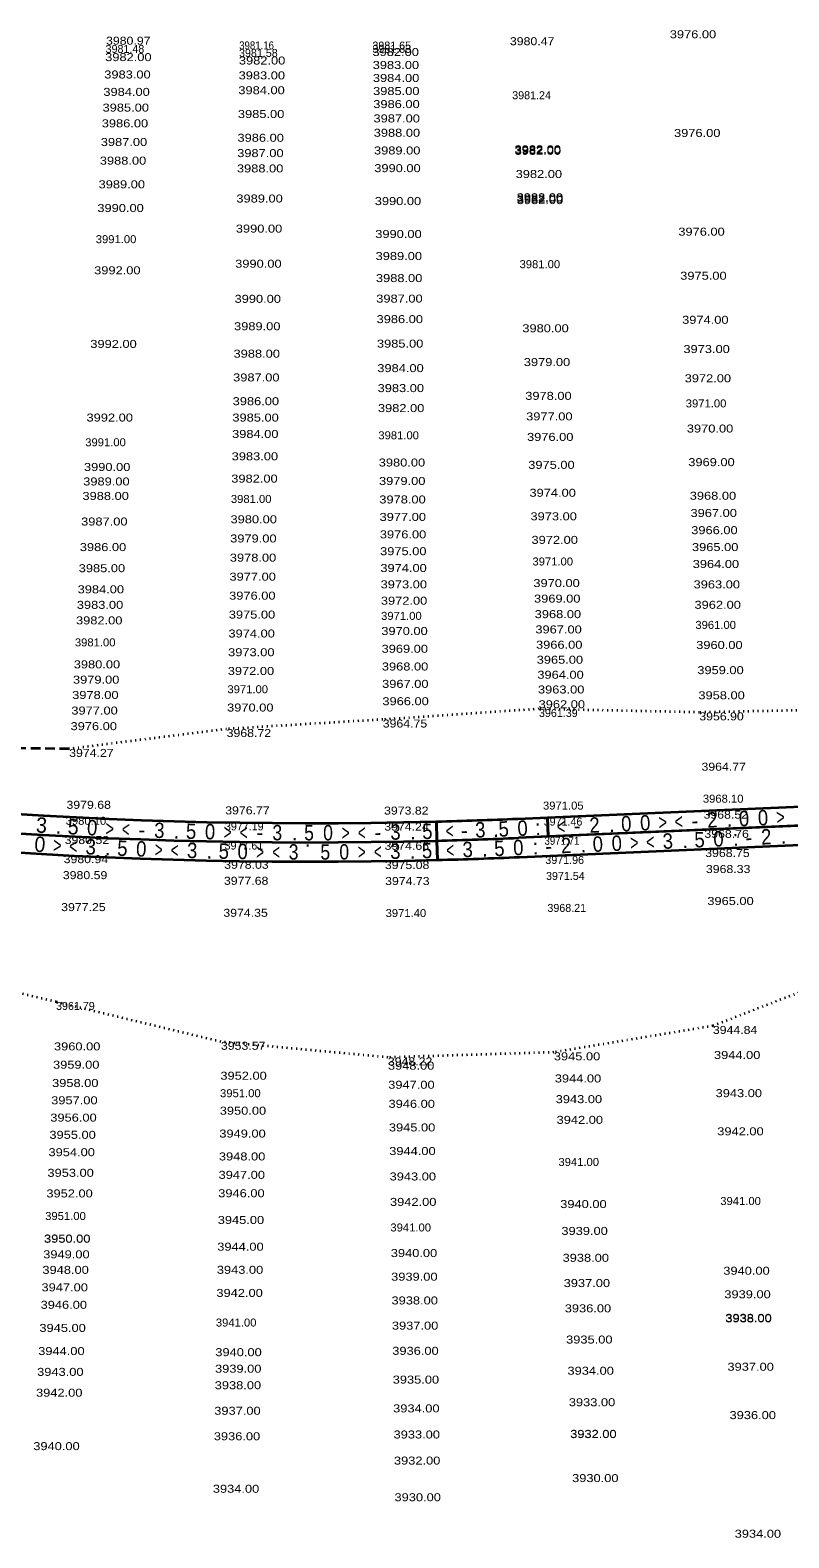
# Model space of a CAD drawing. Extents: x 49942 to 56479, y 47140 to 53283.
# Drawn here: x 52171 to 52645, y 49323 to 50265 of the extents above; entities that cross this region are included whole.
import ezdxf
from ezdxf.enums import TextEntityAlignment as Align

# ---------------------------------------------------------------- set-up
doc = ezdxf.new("R2010")
doc.units = 0
doc.header["$LTSCALE"] = 2
doc.linetypes.add('DOTTED', pattern=[1.5, 0.3, -1.2])
doc.linetypes.add('MEDIUM_DASHED', pattern=[4.5, 3, -1.5])
doc.layers.add('29', color=7, linetype='Continuous')
doc.layers.add('59', color=7, linetype='Continuous', lineweight=35)
doc.layers.add('63', color=7, linetype='Continuous', lineweight=35)

msp = doc.modelspace()

# ---------------------------------------------------------------- linework, layer by layer
at = {"layer": '59', "linetype": 'DOTTED'}
for p, q in [((52488.825, 49841.2), (52391.172, 49834.614)), ((52589.011, 49839.074), (52488.825, 49841.2)), ((52689.019, 49841.052), (52589.011, 49839.074)), ((52293.624, 49828.673), (52195.222, 49816.237)), ((52391.172, 49834.614), (52293.624, 49828.673)), ((52187.039, 49658.165), (52085.276, 49682.412)), ((52695.936, 49681.3), (52597.493, 49643.178)), ((52290.058, 49633.276), (52187.039, 49658.165)), ((52597.493, 49643.178), (52498.113, 49626.686)), ((52394.388, 49623.506), (52290.058, 49633.276)), ((52498.113, 49626.686), (52394.388, 49623.506))]:
    msp.add_line(p, q, dxfattribs=at)
at = {"layer": '59', "linetype": 'MEDIUM_DASHED'}
msp.add_line((52195.222, 49816.237), (52096.806, 49817.413), dxfattribs=at)
at = {"layer": '63'}
for p, q in [((52424.705, 49770.881), (52425.019, 49758.885)), ((52425.019, 49758.885), (52424.705, 49770.881)), ((52425.333, 49746.889), (52425.019, 49758.885)), ((52425.019, 49758.885), (52425.333, 49746.889))]:
    msp.add_line(p, q, dxfattribs=at)
msp.add_lwpolyline([(52494.091, 49773.45), (53576.866, 49820.33), (53577.385, 49808.342), (52494.61, 49761.461)], close=True, dxfattribs=at)
for points in [[(52475.536, 49772.646), (52494.091, 49773.45), (52494.61, 49761.461), (52476.055, 49760.658)], [(52476.574, 49748.669), (52680.665, 49757.505), (52680.146, 49769.494), (52476.055, 49760.658)]]:
    msp.add_lwpolyline(points, dxfattribs=at)
for radius, start, end in [(2975.18, 246.32672, 271.49967), (2987.18, 246.32672, 271.49967), (2987.18, 246.32672, 271.49967), (2999.18, 246.32672, 271.49967), (2975.18, 271.49967, 272.47917), (2987.18, 271.49967, 272.47917), (2987.18, 271.49967, 272.47917), (2999.18, 271.49967, 272.47917)]:
    msp.add_arc((52346.841, 52745.042), radius, start, end, dxfattribs=at)

# ---------------------------------------------------------------- texts
at = {"layer": '29'}
for s, width, p in [('3976.00', 1.2, (52570.56, 50260.218)), ('3980.97', 1.15, (52218.256, 50256.188)), ('3981.16', 0.9, (52301.463, 50253.276)), ('3982.00', 1.2, (52384.782, 50249.128)), ('3980.47', 1.15, (52470.654, 50255.892)), ('3982.00', 1.2, (52217.726, 50245.956)), ('3982.00', 1.2, (52301.29, 50243.822)), ('3983.00', 1.2, (52384.906, 50241.023)), ('3983.00', 1.2, (52217.164, 50235.09)), ('3983.00', 1.2, (52301.121, 50234.537)), ('3984.00', 1.2, (52385.029, 50232.918)), ('3984.00', 1.2, (52216.601, 50224.224)), ('3984.00', 1.2, (52300.952, 50225.251)), ('3985.00', 1.2, (52385.153, 50224.762)), ('3985.00', 1.2, (52216.093, 50214.404)), ('3985.00', 1.2, (52300.681, 50210.407)), ('3986.00', 1.2, (52385.277, 50216.606)), ('3986.00', 1.2, (52215.585, 50204.584)), ('3987.00', 1.2, (52385.414, 50207.645)), ('3987.00', 1.2, (52214.981, 50192.932)), ('3986.00', 1.2, (52300.41, 50195.563)), ('3988.00', 1.2, (52385.55, 50198.683)), ('3976.00', 1.2, (52573.23, 50198.563)), ('3988.00', 1.2, (52214.378, 50181.279)), ('3987.00', 1.2, (52300.235, 50185.987)), ('3989.00', 1.2, (52385.719, 50187.629)), ('3982.00', 1.2, (52473.577, 50188.372)), ('3982.00', 1.2, (52473.587, 50188.149)), ('3982.00', 1.2, (52473.597, 50187.925)), ('3982.00', 1.2, (52473.608, 50187.668)), ('3982.00', 1.2, (52473.619, 50187.412)), ('3988.00', 1.2, (52300.06, 50176.41)), ('3990.00', 1.2, (52385.887, 50176.575)), ('3982.00', 1.2, (52474.247, 50172.906)), ('3989.00', 1.2, (52213.612, 50166.475)), ('3989.00', 1.2, (52299.717, 50157.607)), ('3990.00', 1.2, (52386.2, 50156.01)), ('3982.00', 1.2, (52474.875, 50158.401)), ('3982.00', 1.2, (52474.914, 50157.508)), ('3982.00', 1.2, (52474.952, 50156.614)), ('3990.00', 1.2, (52212.845, 50151.671)), ('3990.00', 1.2, (52299.374, 50138.802)), ('3990.00', 1.2, (52386.514, 50135.444)), ('3976.00', 1.2, (52575.899, 50136.908)), ('3991.00', 1.05, (52211.838, 50132.213)), ('3990.00', 1.2, (52298.974, 50116.873)), ('3989.00', 1.2, (52386.723, 50121.672)), ('3981.00', 1.05, (52476.686, 50116.578)), ('3992.00', 1.2, (52210.831, 50112.755)), ('3988.00', 1.2, (52386.933, 50107.9)), ('3975.00', 1.2, (52577.092, 50109.368)), ('3990.00', 1.2, (52298.574, 50094.944)), ('3987.00', 1.2, (52387.128, 50095.08)), ('3989.00', 1.2, (52298.261, 50077.808)), ('3986.00', 1.2, (52387.324, 50082.26)), ('3974.00', 1.2, (52578.284, 50081.829)), ('3980.00', 1.2, (52478.419, 50076.542)), ('3992.00', 1.2, (52208.45, 50066.757)), ('3988.00', 1.2, (52297.948, 50060.673)), ('3985.00', 1.2, (52387.557, 50066.954)), ('3973.00', 1.2, (52579.075, 50063.564)), ('3984.00', 1.2, (52387.79, 50051.648)), ('3979.00', 1.2, (52479.333, 50055.428)), ('3987.00', 1.2, (52297.677, 50045.83)), ('3972.00', 1.2, (52579.866, 50045.299)), ('3986.00', 1.2, (52297.407, 50030.987)), ('3983.00', 1.2, (52387.98, 50039.165)), ('3978.00', 1.2, (52480.248, 50034.314)), ('3982.00', 1.2, (52388.17, 50026.681)), ('3977.00', 1.2, (52480.803, 50021.49)), ('3971.00', 1.05, (52580.545, 50029.603)), ('3992.00', 1.2, (52206.068, 50020.759)), ('3985.00', 1.2, (52297.22, 50020.75)), ('3970.00', 1.2, (52581.225, 50013.907)), ('3991.00', 1.05, (52205.269, 50005.321)), ('3984.00', 1.2, (52297.033, 50010.513)), ('3981.00', 1.05, (52388.429, 50009.678)), ('3976.00', 1.2, (52481.358, 50008.666)), ('3983.00', 1.2, (52296.779, 49996.566)), ('3969.00', 1.2, (52582.134, 49992.906)), ('3990.00', 1.2, (52204.47, 49989.883)), ('3980.00', 1.2, (52388.688, 49992.675)), ('3975.00', 1.2, (52482.113, 49991.219)), ('3989.00', 1.2, (52204.002, 49980.838)), ('3982.00', 1.2, (52296.524, 49982.619)), ('3979.00', 1.2, (52388.864, 49981.153)), ('3988.00', 1.2, (52203.533, 49971.793)), ('3981.00', 1.05, (52296.292, 49969.913)), ('3978.00', 1.2, (52389.04, 49969.591)), ('3974.00', 1.2, (52482.869, 49973.772)), ('3968.00', 1.2, (52583.043, 49971.906)), ('3987.00', 1.2, (52202.706, 49955.817)), ('3980.00', 1.2, (52296.06, 49957.206)), ('3977.00', 1.2, (52389.206, 49958.683)), ('3973.00', 1.2, (52483.506, 49959.058)), ('3967.00', 1.2, (52583.509, 49961.154)), ('3976.00', 1.2, (52389.372, 49947.775)), ('3966.00', 1.2, (52583.974, 49950.403)), ('3986.00', 1.2, (52201.879, 49939.84)), ('3979.00', 1.2, (52295.842, 49945.221)), ('3975.00', 1.2, (52389.532, 49937.269)), ('3972.00', 1.2, (52484.143, 49944.344)), ('3965.00', 1.2, (52584.432, 49939.842)), ('3978.00', 1.2, (52295.623, 49933.235)), ('3971.00', 1.05, (52484.727, 49930.849)), ('3964.00', 1.2, (52584.889, 49929.281)), ('3985.00', 1.2, (52201.196, 49926.648)), ('3977.00', 1.2, (52295.406, 49921.368)), ('3974.00', 1.2, (52389.692, 49926.762)), ('3984.00', 1.2, (52200.513, 49913.455)), ('3976.00', 1.2, (52295.19, 49909.501)), ('3973.00', 1.2, (52389.848, 49916.549)), ('3970.00', 1.2, (52485.312, 49917.354)), ('3963.00', 1.2, (52585.441, 49916.53)), ('3983.00', 1.2, (52200.011, 49903.749)), ('3972.00', 1.2, (52390.003, 49906.336)), ('3969.00', 1.2, (52485.732, 49907.653)), ('3962.00', 1.2, (52585.993, 49903.779)), ('3982.00', 1.2, (52199.508, 49894.043)), ('3975.00', 1.2, (52294.974, 49897.675)), ('3971.00', 1.05, (52390.148, 49896.87)), ('3968.00', 1.2, (52486.152, 49897.952)), ('3961.00', 1.05, (52586.537, 49891.227)), ('3981.00', 1.05, (52198.797, 49880.309)), ('3974.00', 1.2, (52294.758, 49885.849)), ('3970.00', 1.2, (52390.292, 49887.403)), ('3967.00', 1.2, (52486.566, 49888.393)), ('3973.00', 1.2, (52294.545, 49874.149)), ('3969.00', 1.2, (52390.461, 49876.317)), ('3966.00', 1.2, (52486.979, 49878.835)), ('3960.00', 1.2, (52587.08, 49878.675)), ('3980.00', 1.2, (52198.086, 49866.574)), ('3972.00', 1.2, (52294.331, 49862.448)), ('3968.00', 1.2, (52390.63, 49865.23)), ('3965.00', 1.2, (52487.385, 49869.458)), ('3959.00', 1.2, (52587.76, 49862.963)), ('3979.00', 1.2, (52197.591, 49857.009)), ('3967.00', 1.2, (52390.795, 49854.387)), ('3964.00', 1.2, (52487.791, 49860.08)), ('3978.00', 1.2, (52197.096, 49847.444)), ('3971.00', 1.05, (52294.123, 49851.023)), ('3966.00', 1.2, (52390.96, 49843.544)), ('3963.00', 1.2, (52488.19, 49850.865)), ('3958.00', 1.2, (52588.441, 49847.251)), ('3977.00', 1.2, (52196.592, 49837.704)), ('3970.00', 1.2, (52293.914, 49839.599)), ('3962.00', 1.2, (52488.589, 49841.65)), ('3956.90', 1.15, (52589.011, 49834.074)), ('3976.00', 1.2, (52196.088, 49827.965)), ('3968.72', 1.15, (52293.624, 49823.673)), ('3964.75', 1.15, (52391.172, 49829.614)), ('3974.27', 1.15, (52195.222, 49811.237)), ('3964.77', 1.15, (52590.372, 49802.646)), ('3979.68', 1.15, (52193.544, 49778.827)), ('3971.05', 1.05, (52491.33, 49778.339)), ('3968.10', 1.05, (52591.237, 49782.665)), ('3980.10', 1.05, (52193.027, 49768.84)), ('3976.77', 1.15, (52292.742, 49775.355)), ('3973.82', 1.15, (52392.001, 49775.206)), ('3968.52', 1.15, (52591.669, 49772.675)), ('3974.24', 1.15, (52392.153, 49765.207)), ('3968.76', 1.15, (52592.188, 49760.686)), ('3980.52', 1.15, (52192.407, 49756.856)), ('3974.66', 1.15, (52392.336, 49753.208)), ('3971.71', 0.9, (52492.282, 49756.36)), ('3968.75', 1.15, (52592.707, 49748.697)), ('3980.94', 1.15, (52191.786, 49744.872)), ('3978.03', 1.15, (52292.122, 49741.361)), ('3975.08', 1.15, (52392.519, 49741.209)), ('3968.33', 1.15, (52593.14, 49738.706)), ('3980.59', 1.15, (52191.269, 49734.886)), ('3977.68', 1.15, (52291.939, 49731.362)), ('3974.73', 1.15, (52392.671, 49731.211)), ('3977.25', 1.15, (52190.235, 49714.912)), ('3974.35', 1.15, (52291.574, 49711.366)), ('3971.40', 1.05, (52392.976, 49711.213)), ('3965.00', 1.2, (52594.005, 49718.725)), ('3944.84', 1.15, (52597.493, 49638.178)), ('3960.00', 1.2, (52185.73, 49627.887)), ('3953.57', 1.15, (52290.058, 49628.276)), ('3959.00', 1.2, (52185.138, 49616.459)), ('3948.22', 1.15, (52394.388, 49618.506)), ('3945.00', 1.2, (52498.113, 49621.686)), ('3944.00', 1.2, (52598.171, 49622.522)), ('3952.00', 1.2, (52289.717, 49609.574)), ('3948.00', 1.2, (52394.428, 49615.851)), ('3944.00', 1.2, (52498.711, 49607.873)), ('3958.00', 1.2, (52184.547, 49605.032)), ('3951.00', 1.05, (52289.518, 49598.647)), ('3947.00', 1.2, (52394.609, 49603.935)), ('3943.00', 1.2, (52599.203, 49598.682)), ('3957.00', 1.2, (52183.987, 49594.215)), ('3946.00', 1.2, (52394.791, 49592.02)), ('3943.00', 1.2, (52499.271, 49594.936)), ('3956.00', 1.2, (52183.427, 49583.398)), ('3950.00', 1.2, (52289.318, 49587.719)), ('3942.00', 1.2, (52499.831, 49581.999)), ('3955.00', 1.2, (52182.87, 49572.648)), ('3949.00', 1.2, (52289.057, 49573.431)), ('3945.00', 1.2, (52395.016, 49577.27)), ('3942.00', 1.2, (52600.235, 49574.841)), ('3954.00', 1.2, (52182.309, 49561.799)), ('3944.00', 1.2, (52395.24, 49562.521)), ('3948.00', 1.2, (52288.797, 49559.142)), ('3941.00', 1.05, (52500.97, 49555.695)), ('3953.00', 1.2, (52181.642, 49548.913)), ('3947.00', 1.2, (52288.587, 49547.645)), ('3943.00', 1.2, (52395.482, 49546.634)), ('3952.00', 1.2, (52180.975, 49536.027)), ('3946.00', 1.2, (52288.377, 49536.149)), ('3941.00', 1.05, (52602.121, 49531.289)), ('3951.00', 1.05, (52180.245, 49521.942)), ('3942.00', 1.2, (52395.724, 49530.747)), ('3940.00', 1.2, (52502.109, 49529.392)), ('3945.00', 1.2, (52288.072, 49519.455)), ('3941.00', 1.05, (52395.968, 49514.768)), ('3939.00', 1.2, (52502.836, 49512.605)), ('3950.00', 1.2, (52179.508, 49507.702)), ('3950.00', 1.2, (52179.512, 49507.783)), ('3950.00', 1.2, (52179.516, 49507.857)), ('3949.00', 1.2, (52179.005, 49497.987)), ('3944.00', 1.2, (52287.768, 49502.762)), ('3940.00', 1.2, (52396.211, 49498.789)), ('3938.00', 1.2, (52503.563, 49495.817)), ('3948.00', 1.2, (52178.502, 49488.272)), ('3943.00', 1.2, (52287.504, 49488.315)), ('3940.00', 1.2, (52604.006, 49487.738)), ('3947.00', 1.2, (52177.938, 49477.365)), ('3939.00', 1.2, (52396.436, 49484.013)), ('3937.00', 1.2, (52504.246, 49480.034)), ('3946.00', 1.2, (52177.373, 49466.457)), ('3942.00', 1.2, (52287.241, 49473.869)), ('3938.00', 1.2, (52396.662, 49469.175)), ('3939.00', 1.2, (52604.643, 49473.035)), ('3936.00', 1.2, (52504.93, 49464.25)), ('3938.00', 1.2, (52605.281, 49458.289)), ('3938.00', 1.2, (52605.289, 49458.12)), ('3938.00', 1.2, (52605.296, 49457.951)), ('3945.00', 1.2, (52176.625, 49452.006)), ('3941.00', 1.05, (52286.903, 49455.362)), ('3937.00', 1.2, (52396.902, 49453.439)), ('3944.00', 1.2, (52175.877, 49437.555)), ('3936.00', 1.2, (52397.142, 49437.704)), ('3935.00', 1.2, (52505.774, 49444.756)), ('3940.00', 1.2, (52286.565, 49436.854)), ('3937.00', 1.2, (52606.604, 49427.746)), ('3943.00', 1.2, (52175.204, 49424.55)), ('3939.00', 1.2, (52286.377, 49426.53)), ('3935.00', 1.2, (52397.415, 49419.717)), ('3934.00', 1.2, (52506.618, 49425.262)), ('3942.00', 1.2, (52174.53, 49411.544)), ('3938.00', 1.2, (52286.188, 49416.206)), ('3937.00', 1.2, (52285.897, 49400.261)), ('3934.00', 1.2, (52397.69, 49401.731)), ('3933.00', 1.2, (52507.47, 49405.577)), ('3936.00', 1.2, (52607.911, 49397.541)), ('3936.00', 1.2, (52285.607, 49384.317)), ('3933.00', 1.2, (52397.938, 49385.431)), ('3932.00', 1.2, (52508.325, 49385.827)), ('3932.00', 1.2, (52508.328, 49385.755)), ('3932.00', 1.2, (52508.331, 49385.683)), ('3940.00', 1.2, (52172.802, 49378.164)), ('3932.00', 1.2, (52398.186, 49369.131)), ('3930.00', 1.2, (52509.521, 49358.19)), ('3934.00', 1.2, (52285.008, 49351.522)), ('3930.00', 1.2, (52398.535, 49346.225)), ('3934.00', 1.2, (52611.12, 49323.43))]:
    msp.add_text(s, height=5, dxfattribs=dict(at, width=width)).set_placement(p)
for s, p in [('3981.48', (52217.991, 50251.072)), ('3981.58', (52301.377, 50248.552)), ('3981.65', (52384.721, 50253.15)), ('3981.83', (52384.751, 50251.139)), ('3981.24', (52472.116, 50222.132)), ('3961.39', (52488.825, 49836.2)), ('3971.46', (52491.763, 49768.349)), ('3977.19', (52292.56, 49765.357)), ('3977.61', (52292.341, 49753.359)), ('3971.96', (52492.801, 49744.371)), ('3971.54', (52493.234, 49734.381)), ('3968.21', (52494.099, 49714.399)), ('3961.79', (52187.039, 49653.165))]:
    msp.add_text(s, height=5, dxfattribs=at).set_placement(p)
at = {"layer": '63'}
for s, rotation, width, p in [('3', 356.748, 0.95, (52177.702, 49763.858)), ('5', 357.13, 0.95, (52197.556, 49762.798)), ('0', 357.358, 0.9, (52209.409, 49762.229)), ('0', 2.466, 0.9, (52478.767, 49761.976)), ('2', 2.479, 0.9, (52523.754, 49763.924)), ('0', 2.479, 0.9, (52543.578, 49764.782)), ('0', 2.479, 0.9, (52555.41, 49765.295)), ('>', 2.479, 0.7, (52566.344, 49765.768)), ('<', 2.479, 0.7, (52576.382, 49766.203)), ('2', 2.479, 0.9, (52597.355, 49767.111)), ('0', 2.479, 0.9, (52617.178, 49767.969)), ('0', 2.479, 0.9, (52629.01, 49768.481)), ('>', 2.479, 0.7, (52639.945, 49768.955)), ('>', 357.569, 0.7, (52220.365, 49761.743)), ('<', 357.762, 0.65, (52230.424, 49761.334)), ('3', 358.166, 0.9, (52251.445, 49760.589)), ('5', 358.548, 0.9, (52271.319, 49760.02)), ('0', 358.776, 0.9, (52283.183, 49759.743)), ('>', 358.987, 0.65, (52294.148, 49759.528)), ('<', 359.181, 0.65, (52304.214, 49759.367)), ('3', 359.585, 0.85, (52325.247, 49759.142)), ('5', 359.967, 0.85, (52345.129, 49759.065)), ('0', 0.195, 0.85, (52357.028, 49759.082)), ('>', 0.406, 0.65, (52368.03, 49759.138)), ('<', 0.599, 0.65, (52378.13, 49759.227)), ('3', 1.004, 0.9, (52399.23, 49759.524)), ('5', 1.386, 0.9, (52419.172, 49759.94)), ('<', 1.654, 0.65, (52433.175, 49760.312)), ('3', 2.021, 0.9, (52452.305, 49760.927)), ('5', 2.302, 0.9, (52466.969, 49761.482)), ('<', 2.479, 0.7, (52502.782, 49763.016)), ('3', 2.479, 0.9, (52569.535, 49753.895)), ('5', 2.479, 0.9, (52589.359, 49754.753)), ('0', 2.479, 0.9, (52601.191, 49755.266)), ('2', 2.479, 0.9, (52631.052, 49756.558)), ('0', 356.741, 0.95, (52176.689, 49751.897)), ('>', 356.95, 0.7, (52187.595, 49751.296)), ('<', 357.142, 0.7, (52197.609, 49750.78)), ('3', 357.351, 0.9, (52208.52, 49750.257)), ('5', 357.73, 0.9, (52228.304, 49749.409)), ('0', 357.957, 0.9, (52240.115, 49748.964)), ('>', 358.166, 0.65, (52251.031, 49748.594)), ('<', 358.358, 0.65, (52261.054, 49748.291)), ('3', 358.567, 0.9, (52271.973, 49747.999)), ('5', 358.946, 0.9, (52291.771, 49747.57)), ('0', 359.172, 0.9, (52303.588, 49747.376)), ('>', 359.381, 0.65, (52314.51, 49747.238)), ('<', 359.573, 0.65, (52324.537, 49747.146)), ('3', 359.782, 0.85, (52335.46, 49747.086)), ('5', 0.161, 0.85, (52355.289, 49747.076)), ('0', 0.387, 0.85, (52367.146, 49747.133)), ('>', 0.597, 0.65, (52378.104, 49747.226)), ('<', 0.788, 0.65, (52388.162, 49747.348)), ('3', 0.998, 0.9, (52399.119, 49747.52)), ('5', 1.377, 0.9, (52418.981, 49747.932)), ('<', 1.653, 0.65, (52433.457, 49748.315)), ('3', 1.862, 0.9, (52444.41, 49748.652)), ('5', 2.241, 0.9, (52464.264, 49749.365)), ('0', 2.436, 0.9, (52476.108, 49749.851)), ('2', 2.479, 0.9, (52505.973, 49751.143)), ('0', 2.479, 0.9, (52525.797, 49752.001)), ('0', 2.479, 0.9, (52537.628, 49752.513)), ('>', 2.479, 0.7, (52548.563, 49752.987)), ('<', 2.479, 0.7, (52558.601, 49753.422))]:
    msp.add_text(s, height=9.6, rotation=rotation, dxfattribs=dict(at, width=width)).set_placement(p, align=Align.CENTER)
for s, rotation, p in [('.', 356.939, (52188.382, 49763.27)), ('-', 357.955, (52240.485, 49760.958)), ('-', 359.374, (52314.28, 49759.241)), ('-', 0.793, (52388.229, 49759.35)), ('-', 1.829, (52442.29, 49760.589)), ('.', 2.19, (52461.96, 49761.282)), (':', 2.479, (52488.353, 49762.391)), ('-', 2.479, (52512.82, 49763.45)), ('.', 2.479, (52534.469, 49764.388)), ('-', 2.479, (52586.42, 49766.637)), ('.', 2.479, (52608.07, 49767.575)), (':', 2.479, (52611.906, 49755.729)), ('.', 358.357, (52262.256, 49760.26)), ('.', 359.776, (52336.181, 49759.081)), ('.', 179.972, (52344.352, 49756.663)), ('.', 1.195, (52410.113, 49759.733)), (':', 2.479, (52486.826, 49750.314)), ('-', 2.479, (52495.038, 49750.669)), ('.', 2.479, (52516.688, 49751.607)), ('.', 2.479, (52580.25, 49754.359)), ('-', 2.479, (52620.118, 49756.085)), ('.', 2.479, (52641.768, 49757.022)), ('.', 357.541, (52219.216, 49749.78)), ('.', 358.756, (52282.779, 49747.747)), ('.', 1.187, (52409.962, 49747.727)), ('.', 2.052, (52455.177, 49749.02))]:
    msp.add_text(s, height=9.6, rotation=rotation, dxfattribs=at).set_placement(p, align=Align.CENTER)

doc.saveas('drawing.dxf')
